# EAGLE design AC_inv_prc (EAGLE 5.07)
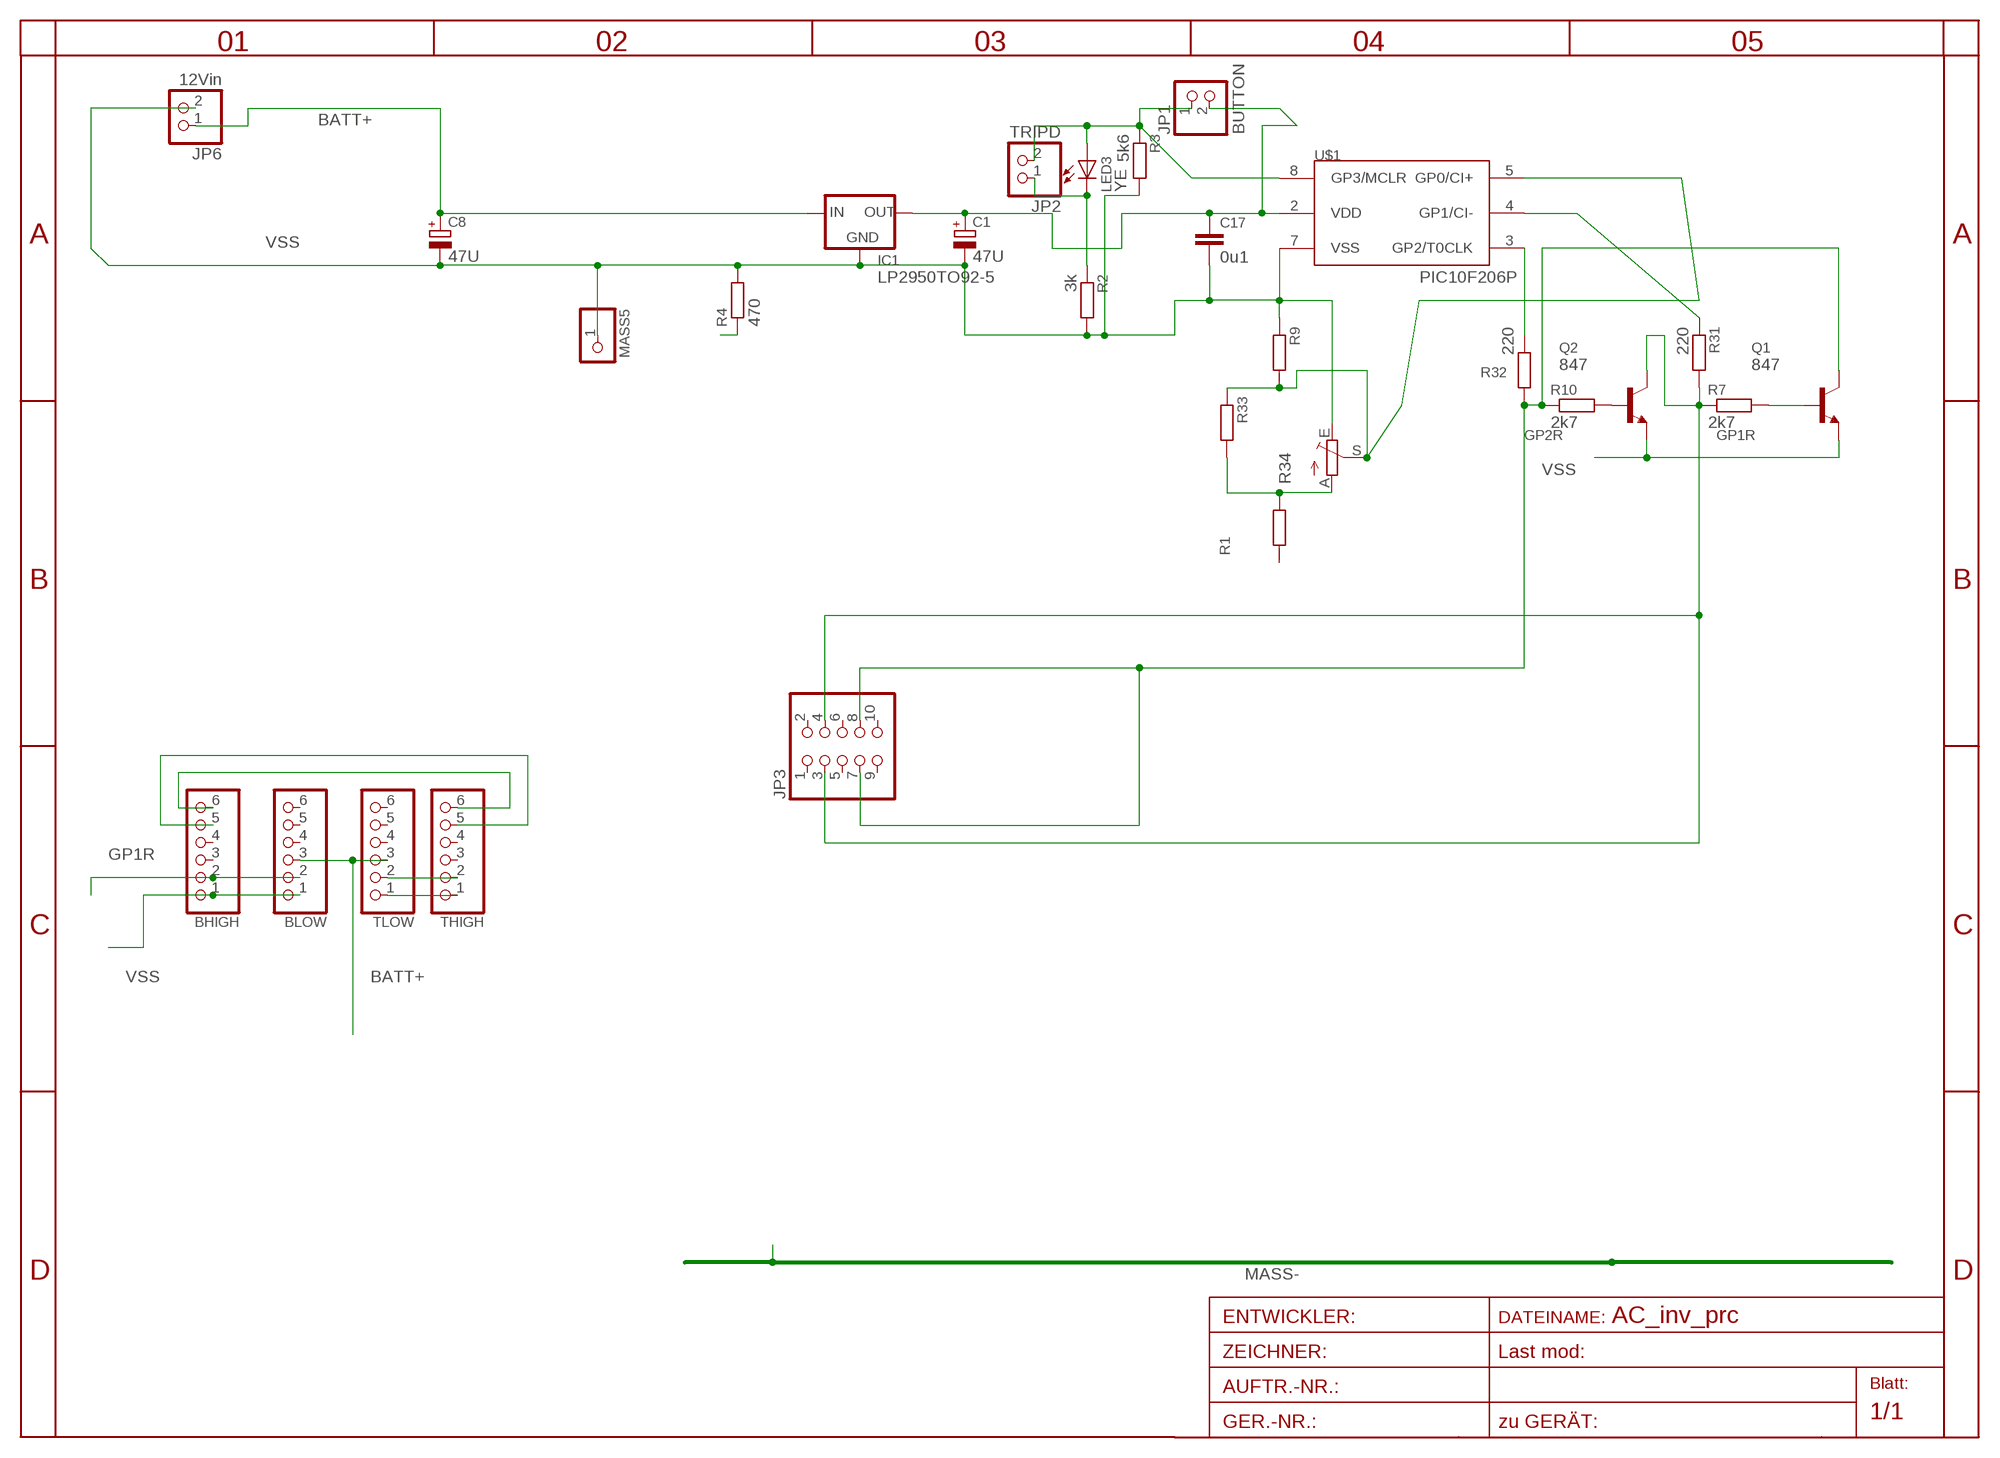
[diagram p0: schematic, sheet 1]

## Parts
BHIGH  PINHD-1X6  [1X06BOX]
BLOW  PINHD-1X6  [1X06BOX]
C1  47U  CPOL-EUE5-6  [E5-6]
C8  47U  CPOL-EUE5-5  [E5-5]
C17  0u1  C-EUC1206  [C1206]
IC1  LP2950TO92-5  [T092-5]
JP1  BUTTON  PINHD-1X2/90  [1X02/90]
JP2  TRIPD  PINHD-1X2/90  [1X02/90]
JP3  PINHD-2X5  [2X05]
JP6  12Vin  PINHD-1X2STR  [1X02]
LED3  YE  LEDCHIPLED_1206  [CHIPLED_1206]
MASS5  PINHD-1X11MM6  [1X1MM8]
Q1  847  BC847ALT1SMD  [SOT23]
Q2  847  BC847ALT1SMD  [SOT23]
R1  R-EU_0207/35  [0207/35]
R2  3k  R-EU_R0805  [R0805]
R3  5k6  R-EU_R0805  [R0805]
R4  470  R-EU_0204/5  [0204/5]
R7  2k7  R-EU_R0805  [R0805]
R9  R-EU_R0805  [R0805]
R10  2k7  R-EU_R0805  [R0805]
R31  220  R-EU_R1206  [R1206]
R32  220  R-EU_R1206  [R1206]
R33  R-EU_R0805  [R0805]
R34  TRIM_EU-S64W  [S64W]
THIGH  PINHD-1X6  [1X06BOX]
TLOW  PINHD-1X6  [1X06BOX]
U$1  PIC10F206P  [DIL8]

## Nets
BATT+: BLOW.3 C8.+ IC1.3(IN) JP6.1 TLOW.3
GP1R: BHIGH.2 BLOW.2 JP3.3 JP3.4 Q2.3(C) R7.1 R31.2
GP2R: JP3.7 JP3.8 Q1.3(C) R10.1 R32.2 THIGH.2 TLOW.2
GP3: BHIGH.6 JP1.1 JP2.2 LED3.A R3.1 THIGH.6 U$1.8(GP3/MCLR)
N$1: R9.2 R33.1 R34.S U$1.5(GP0/CI+)
N$4: Q2.1(B) R10.2
N$7: Q1.1(B) R7.2
N$15: JP2.1 LED3.C R2.1
N$34: R4.1
N$39: R31.1 U$1.4(GP1/CI-)
N$42: R1.1 R33.2 R34.A
N$43: R32.1 U$1.3(GP2/T0CLK)
VDD: BHIGH.5 C1.+ C17.1 IC1.1(OUT) JP1.2 THIGH.5 U$1.2(VDD)
VSS: BHIGH.1 BLOW.1 C1.- C8.- C17.2 IC1.2(GND) JP6.2 MASS5.1 Q1.2(E) Q2.2(E) R2.2 R3.2 R4.2 R9.1 R34.E THIGH.1 TLOW.1 U$1.7(VSS)
Unconnected: BHIGH.3 BHIGH.4 BLOW.4 BLOW.5 BLOW.6 JP3.1 JP3.2 JP3.5 JP3.6 JP3.9 JP3.10 R1.2 THIGH.3 THIGH.4 TLOW.4 TLOW.5 TLOW.6

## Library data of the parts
BHIGH BLOW THIGH TLOW = pinhead:PINHD-1X6: PIN HEADER
C1 C8 = rcl-2:CPOL-EU: POLARIZED CAPACITOR, European symbol
C17 = rcl-2:C-EU: CAPACITOR, European symbol
IC1 = v-reg:LP2950?*: Source: http://cache.national.com/ds/LP/LP2950.pdf
JP1 JP2 JP6 = pinhead:PINHD-1X2: PIN HEADER
JP3 = pinhead:PINHD-2X5: PIN HEADER
LED3 = led:LED: LED
MASS5 = pinhead:PINHD-1X1: PIN HEADER
Q1 Q2 = transistor-npn:BC847*: NPN Transistor
R1-R4 R7 R9 R10 R31-R33 = rcl-2:R-EU_: RESISTOR, European symbol
R34 = pot:TRIM_EU-: POTENTIOMETER
U$1 = microchip-5:PIC10F2*: uPC nW 0,25/0,5k Program Flash memory Comparator

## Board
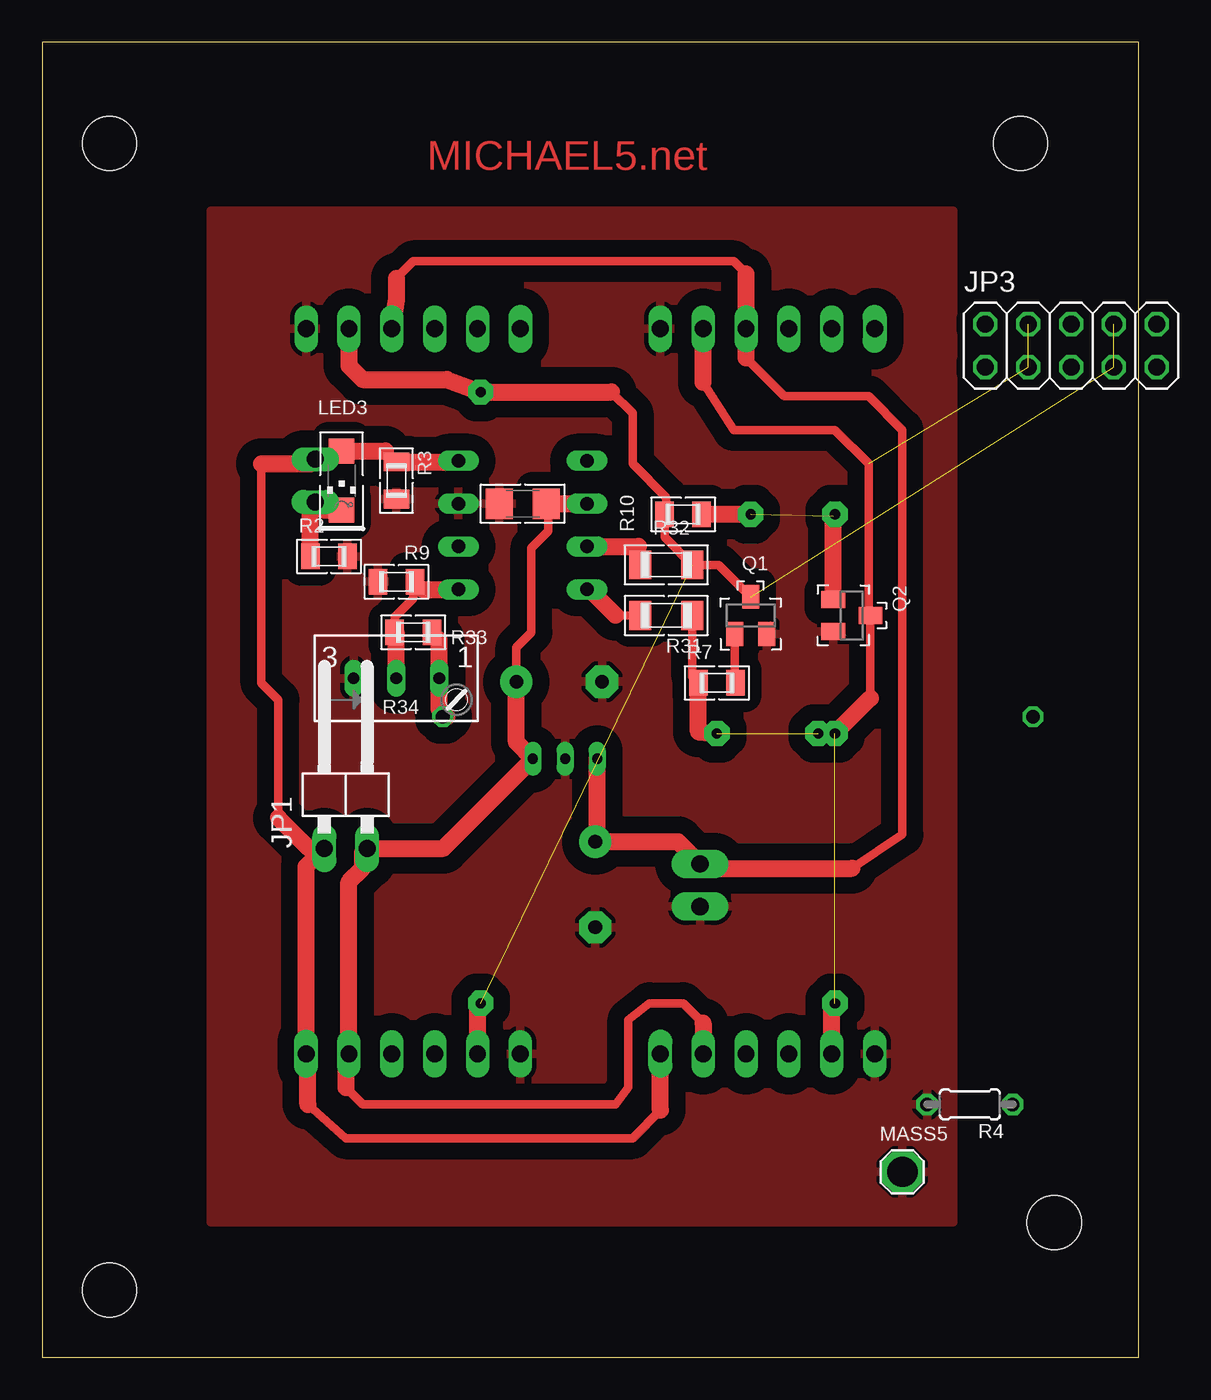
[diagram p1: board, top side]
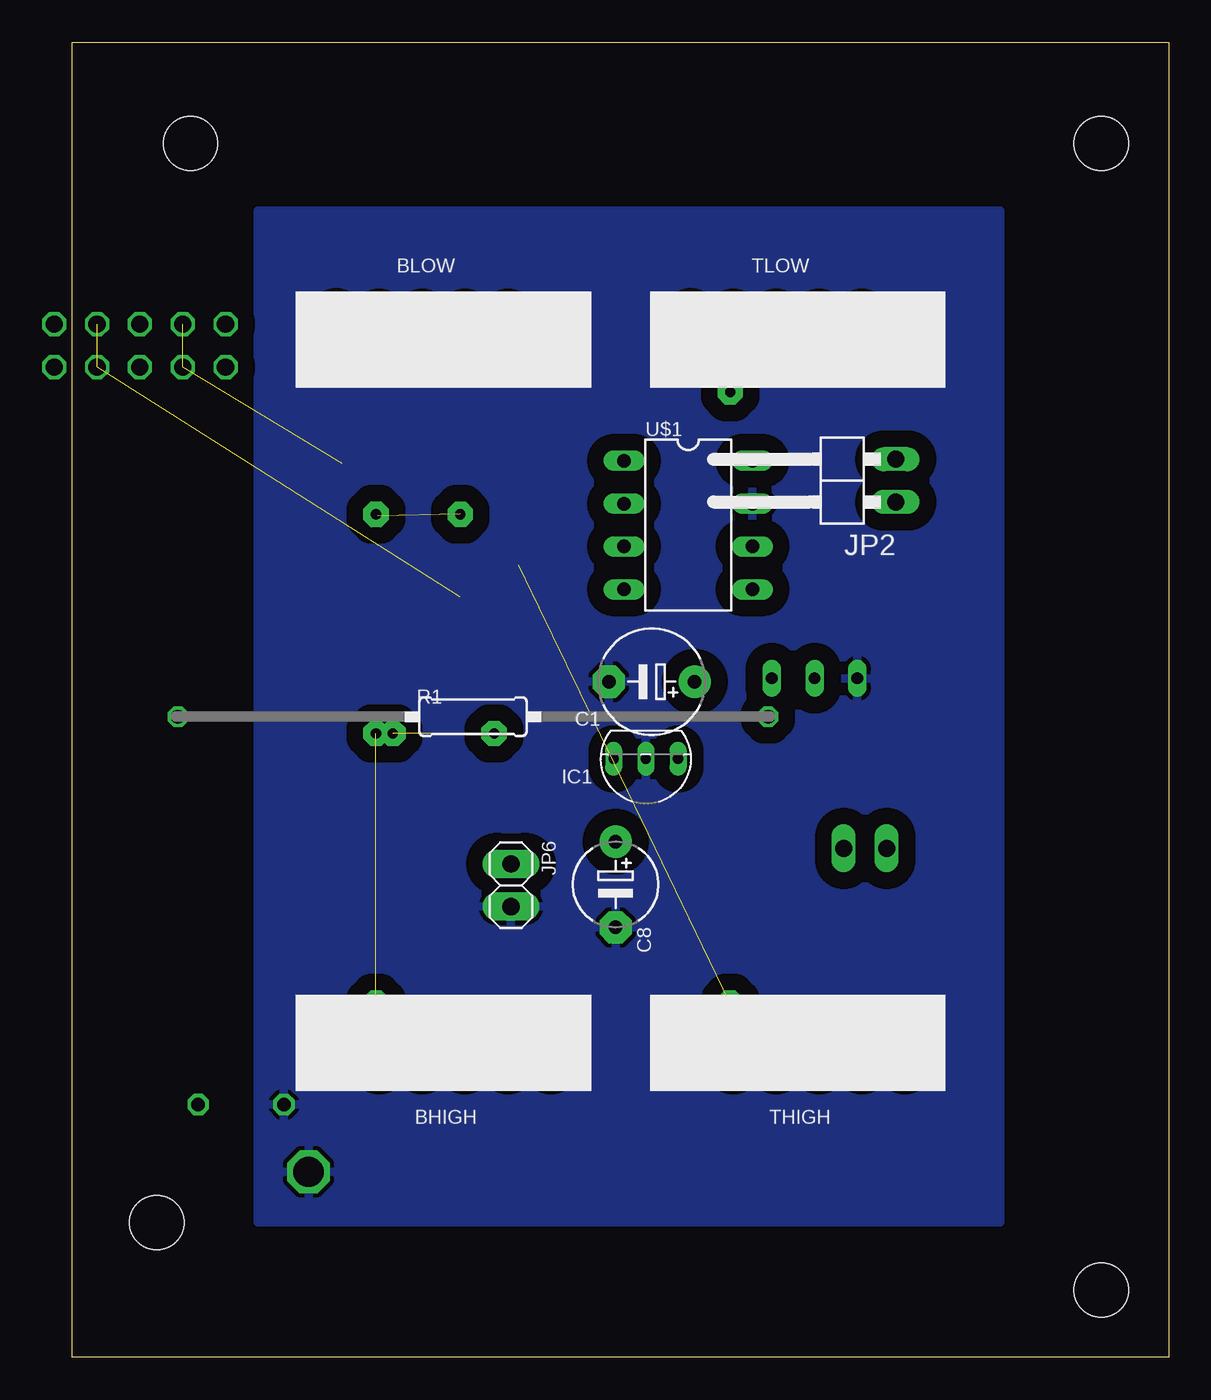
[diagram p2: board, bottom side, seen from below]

Size 65 x 78 mm. Coordinates in mm from the lower left corner, seen from the top.
Outline: 0,0 65,0 65,78 0,78 0,0
Copper layers (1*16): Top 0.035mm / dielectric 1.5mm / Bottom 0.035mm
Design rules "default *": minimum track width 12mil, minimum drill 24mil, track to track 8mil, track to pad 8mil, pad to pad 8mil, via to via 8mil, smd to smd 8mil, copper to edge 40mil, drill to drill 8mil, minimum pad ring 8mil, minimum via ring 8mil, stop-mask expansion 4mil, vias tented up to drill 0mil, thermal gap 10mil
Holes 3.2 mm at 4,72 4,4 58,72 60,8

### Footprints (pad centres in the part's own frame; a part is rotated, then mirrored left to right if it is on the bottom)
1X06BOX = drill 1 long: 1 -6.35,0; 2 -3.81,0; 3 -1.27,0; 4 1.27,0; 5 3.81,0 | drill 1.016 long: 6 6.35,0
E5-6 = drill 0.813 pad 1.905 round: + -2.54,0 | drill 0.813 pad 1.905 octagon: - 2.54,0
E5-5 = drill 0.813 pad 1.905 round: + -2.54,0 | drill 0.813 pad 1.905 octagon: - 2.54,0
C1206 = smd 1.6 x 1.8: 1 -1.4,0; 2 1.4,0
T092-5 = drill 0.6 pad 0.813 long: 1 -1.905,0; 2 0,0; 3 1.905,0
1X02/90 = drill 1.016 long: 1 -1.27,-3.81; 2 1.27,-3.81
2X05 = drill 1.016 octagon: 1 -5.08,-1.27; 2 -5.08,1.27; 3 -2.54,-1.27; 4 -2.54,1.27; 5 0,-1.27; 6 0,1.27; 7 2.54,-1.27; 8 2.54,1.27; 9 5.08,-1.27; 10 5.08,1.27
1X02 = drill 1.016 pad 1.676 long: 1 -1.27,0; 2 1.27,0
CHIPLED_1206 = smd 1.5 x 1.5: A 0,-1.75; C 0,1.75
1X1MM8 = drill 1.8 pad 2.54 octagon: 1 0,0
SOT23 = smd 1 x 1.4: 1 -0.95,-1.1; 2 0.95,-1.1; 3 0,1.1
0207/35 = drill 0.813 octagon: 1 -17.5,0; 2 17.5,0
R0805 = smd 1.1 x 1.5: 1 -1.1,0; 2 1.1,0
0204/5 = drill 0.8 pad 1.27 octagon: 1 -2.54,0; 2 2.54,0
R1206 = smd 1.3 x 1.7: 1 -1.55,0; 2 1.55,0
S64W = drill 0.7 long: A 2.54,1.27; E -2.54,1.27; S 0,1.27
DIL8 = drill 0.8 long: 1 -3.81,-3.81; 2 -1.27,-3.81; 3 1.27,-3.81; 4 3.81,-3.81; 5 3.81,3.81; 6 1.27,3.81; 7 -1.27,3.81; 8 -3.81,3.81

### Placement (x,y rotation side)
BHIGH  43,18 0 bottom
BLOW  43,61 180 bottom
C1  30.65,40.07 180 bottom
C8  32.8,28.05 270 bottom
C17  28.49,50.63 180 top
IC1  31,35.5 180 bottom
JP1  18,34 0 top
JP2  20,52 90 bottom
JP3  61,60 0 top
JP6  39,28 270 bottom
LED3  17.75,52 180 top
MASS5  51,11 0 top
Q1  42,44 0 top
Q2  48,44 270 top
R1  41.25,38 180 bottom
R2  17,47.5 0 top
R3  21,52 270 top
R4  55,15 180 top
R7  40,40 0 top
R9  21,46 0 top
R10  38,50 0 top
R31  37,44 0 top
R32  37,47 0 top
R33  22,43 0 top
R34  21,39 0 top
THIGH  22,18 0 bottom
TLOW  22,61 180 bottom
U$1  28.49,49.36 270 bottom

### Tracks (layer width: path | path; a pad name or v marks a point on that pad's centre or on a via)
BATT+
  Top 0.5: 41.73,59.27 44,57 49,57 51,55 51,31 48,29 | JP6.1 39.27,29 | 41.73,64.27 41,65 22,65 21,64 | C8.+ 32.91,30.7
  Top 1: 41.73,59.27 BLOW.3 41.73,64.27 | 39.27,29 48,29 | 21,64 21,62.73 TLOW.3 | 32.91,30.7 IC1.3 | C8.+ 37.69,30.59 JP6.1
GP1R  (via drill 0.6 pad 1.5)  (4 unrouted)
  Top 0.5: 46.81,20.81 v47,21 | 39.19,57.81 41,55 47,55 49,53 49,44 49.1,44.1 Q2.3 49.1,39.1 | R31.2 38.55,40.35 R7.1
  Top 1: BHIGH.2 46.81,20.81 | R7.1 38.9,37.1 v40,37 | v46,37 v47,37 49.1,39.1 | 39.19,57.81 BLOW.2
GP2R  (via drill 0.6 pad 1.5)  (3 unrouted)
  Top 0.5: 25.81,20.81 v26,21 | Q1.3 40.1,47 R32.2 36.9,48.65 R10.1 37,50.1 37,51 35,53 35,56 33.75,57.25
  Top 1: THIGH.2 25.81,20.81 | TLOW.2 18.19,58.81 19,58 24,58 v26,57.25 33.75,57.25
GP3
  Top 0.5: 36.65,14.65 35,13 18,13 15.75,15 | 15.75,17.65 THIGH.6 | JP1.1 15.81,30.19 | 14,32 14,39 13,40 13,53 | 15.92,53 JP2.2 17.27,53.27 LED3.A | 20.35,53.75 R3.1 | 24.61,53.1 U$1.8
  Top 1: 36.65,14.65 BHIGH.6 | 15.75,15 15.75,17.65 | THIGH.6 15.65,29.11 JP1.1 | 15.81,30.19 14,32 | 13,53 15.92,53 | LED3.A 20.35,53.75 | R3.1 24.61,53.1
N$1
  Top 0.5: 21,42.9 R33.1 20.9,43.9 22,45 22,45.9 R9.2 22.55,45.55
  Top 1: R34.S 21,42.9 | 22.55,45.55 U$1.5
N$4  (via drill 0.6 pad 1.5)  (1 unrouted)
  Top 0.5: 46.9,49.9 v47,50
  Top 1: Q2.1 46.9,49.9 | R10.2 v42,50
N$7
  Top 0.5: Q1.1 41.05,40.05 R7.2
N$15
  Top 0.5: 15.9,50.44 JP2.1 16.67,50.25
  Top 1: R2.1 15.9,50.44 | 16.67,50.25 LED3.C
N$39
  Top 0.5: U$1.4 32.45,45.55 | 34,44 R31.1
  Top 1: 32.45,45.55 34,44
N$42
  Top 0.5: 23.54,42.56 R33.2 | 24,38 23.54,38.46
  Top 1: 23.54,42.56 R34.A 23.54,38.46 | R1.1 24,38
N$43
  Top 0.5: 35.36,48.09 R32.1
  Top 1: U$1.3 35.36,48.09
VDD
  Top 0.5: 19,29.92 JP1.2 | C1.+ 28.11,42.11 29,43 29,48 30,49 30,50.52 C17.1 | 39.19,19.81 38,21 36,21 34.75,20 34.75,16 34,15 19,15 18,16 | 18,17.81 THIGH.5
  Top 1: THIGH.5 18.19,28.19 19,29 19,29.92 | JP1.2 23.79,30.19 IC1.1 28.11,36.48 C1.+ | C17.1 U$1.2 | 39.19,19.81 BHIGH.5 | 18,17.81 18,16
VSS
  pour Top (isolate 1): 10,68 54,68 54,8 10,8
  pour Bottom (isolate 1): 10,68 54,68 54,8 10,8

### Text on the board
Top: MICHAEL5.net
